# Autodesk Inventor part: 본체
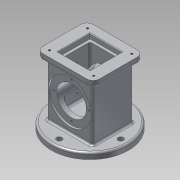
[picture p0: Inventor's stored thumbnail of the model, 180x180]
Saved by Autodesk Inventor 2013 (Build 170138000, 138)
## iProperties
Created: 2018-10
Part Number: 본체
Material: 알루미늄 6061
Document SubType Name: Modeling
Designer: Administrator
Density: 2.71 g/cm^3
Mass: 988.226 g
Surface Area: 743.905 cm^2
Volume: 364.659 cm^3
Author: Administrator
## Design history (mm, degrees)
sketch "스케치1"
  geometry: C1 r 62.5 at (0, 0); 1 further point
  constraints: 1 centre point, 1 coincident
  dimensions: "d0" = 125 diameter of C1
extrude "돌출1" new body sketch "스케치1" distance "d1" = 10; taper "d2" = 0 deg
sketch "스케치2"
  geometry: L1 (-37, -33)-(37, -33); L2 (37, -33)-(37, 33); L3 (37, 33)-(-37, 33); L4 (-37, 33)-(-37, -33); C1 r 62.5 at (0, 0) reference; 2 further points
  constraints: 8 end point, 2 midpoint, 2 parallel, 1 horizontal, 1 horizontal alignment, 1 perpendicular, 1 vertical alignment
  dimensions: "d3" = 74 distance of L3.end L2.end; "d4" = 66 distance of L2.end L1.end
extrude "돌출2" join sketch "스케치2" distance "d5" = 88; taper "d6" = 0 deg
sketch "스케치3"
  geometry: L1 (-46, -41)-(46, -41); L2 (46, -41)-(46, 41); L3 (46, 41)-(-46, 41); L4 (-46, 41)-(-46, -41); 3 further points
  constraints: 8 end point, 2 midpoint, 2 parallel, 1 horizontal, 1 horizontal alignment, 1 perpendicular, 1 vertical alignment
  dimensions: "d7" = 92 distance of L3.end L2.end; "d8" = 82 distance of L2.end L1.end
extrude "돌출3" join sketch "스케치3" distance "d9" = 10; taper "d10" = 0 deg
sketch "스케치4"
  geometry: L1 (-26, -26)-(26, -26); L2 (26, -26)-(26, 26); L3 (26, 26)-(-26, 26); L4 (-26, 26)-(-26, -26); 3 further points
  constraints: 8 end point, 2 midpoint, 2 parallel, 1 horizontal, 1 horizontal alignment, 1 perpendicular, 1 vertical alignment
  dimensions: "d11" = 52 distance of L3.end L2.end; "d12" = 52 distance of L2.end L1.end
extrude "돌출4" cut sketch "스케치4" distance "d13" = 8; taper "d14" = 0 deg
sketch "스케치5"
  geometry: L1 (-22, -22)-(22, -22); L2 (22, -22)-(22, 22); L3 (22, 22)-(-22, 22); L4 (-22, 22)-(-22, -22); L5 (-46, -41)-(46, -41) reference; L6 (-46, 41)-(-46, -41) reference; L7 (46, 41)-(-46, 41) reference; L8 (46, -41)-(46, 41) reference; L9 (-37, 33)-(-37, -33) reference; L10 (-37, -33)-(37, -33) reference; L11 (37, -33)-(37, 33) reference; L12 (37, 33)-(-37, 33) reference; 3 further points
  constraints: 8 end point, 2 midpoint, 2 parallel, 1 horizontal, 1 horizontal alignment, 1 perpendicular, 1 vertical alignment
  dimensions: "d15" = 44 distance of L2.end L3.end; "d17" = 44 distance of L3.end L1.start
extrude "돌출5" cut sketch "스케치5" distance "d18" = 74; taper "d19" = 0 deg
sketch "스케치6"
  geometry: C1 r 62.5 at (0, 0) reference; C2 r 28 at (0, 0)
  constraints: 1 centre point, 1 coincident
  dimensions: "d20" = 56 diameter of C2
extrude "돌출6" cut sketch "스케치6" distance "d21" = 18; taper "d22" = -10 deg
sketch "스케치8"
  geometry: L1 (-25.5, -10)-(99.5, -10) reference; C1 r 35 at (37, 44); 2 further points
  constraints: 1 centre point, 1 midpoint, 1 vertical alignment
  dimensions: "d25" = 70 diameter of C1; "d26" = 54 distance from line of L1 C1.centre
extrude "돌출7" cut sketch "스케치8" distance "d27" = 3; taper "d28" = 0 deg
sketch "스케치9"
  geometry: C1 r 35 at (0, 0) reference; C2 r 24 at (0, 0); 1 further point
  constraints: 1 centre point, 1 coincident
  dimensions: "d29" = 48 diameter of C2
extrude "돌출8" cut sketch "스케치9" stored distance "d30" = 3; taper "d31" = 0 deg
sketch "스케치10"
  geometry: C1 r 24 at (0, 0) reference; 2 further points
  constraints: 1 vertical alignment
  dimensions: "d32" = 29 distance of point (0, 29) C1.centre
hole "구멍1" sketch "스케치10" at (0, 29) diameter "d33" = 3.242; stored, may be unused: countersink angle "d37" = 90 deg, drill point angle "d39" = 118 deg; dims "d34" = 4, "d35" = 4, "d36" = 2, "d38" = 6
sketch "스케치11"
  geometry: C1 r 62.5 at (0, 0) reference; C2 r 4.5 at (-50, 0)
  constraints: 1 centre point
  dimensions: "d43" = 50 distance of C2.centre C1.centre; "d44" = 9 diameter of C2
extrude "돌출9" cut sketch "스케치11" stored distance "d45" = 3; taper "d46" = 0 deg
sketch "스케치13"
  geometry: 2 further points
  dimensions: "d59" = 31 vertical distance of point (-35, 31) point (0, 0); "d60" = 35 horizontal distance of point (0, 0) point (-35, 31)
hole "구멍3" sketch "스케치13" at (-35, 31) diameter "d61" = 3.242; stored, may be unused: countersink angle "d65" = 90 deg, drill point angle "d67" = 118 deg; dims "d62" = 4, "d63" = 4, "d64" = 2, "d66" = 6
fillet "모깎기1" dims "d74" = 10
fillet "모깎기2" dims "d75" = 3
fillet "모깎기3" dims "d76" = 3
fillet "모깎기4" dims "d77" = 3
fillet "모깎기5" dims "d78" = 3
fillet "모깎기6" dims "d79" = 3
fillet "모깎기7" dims "d80" = 3
sketch "스케치14"
  geometry: L1 (72, 0)-(0, 0) reference; L2 (82, 0)-(82, 7) reference; 2 further points
  constraints: 1 other
  dimensions: "d81" = 4 distance from line of L1 point (36, 4); "d82" = 46 distance from line of point (36, 4) L2
feature "엠보싱1" sketch "스케치14" dims "d1" = 10, "d83" = 0.5, "d84" = 0
sketch "스케치15"
  geometry: L1 (-95, 92.5)-(-95, -32.5) reference; 4 further points
  constraints: 2 horizontal alignment, 1 midpoint
  dimensions: "d85" = 43 distance of point (-15, 30) point (-58, 30); "d87" = 37 distance from line of point (-58, 30) L1
hole "구멍4" sketch "스케치15" at (-15, 30), (-58, 30) diameter "d88" = 4.134; stored, may be unused: countersink angle "d92" = 90 deg, drill point angle "d94" = 118 deg; dims "d89" = 20, "d90" = 4, "d91" = 2, "d93" = 20
chamfer "모따기1" distance "d95" = 1; stored, may be unused: second distance "d96" = 2, angle "d97" = 45 deg
node "솔리드1"
mirror "대칭1"
pattern_circular "원형 패턴1" dims angle "d41" = 360 deg
mirror "대칭2"
pattern_circular "원형 패턴2" dims angle "d48" = 360 deg
pattern_linear "직사각형 패턴1" dims "d70" = 72, "d73" = 62
node "투영된 루프1"
